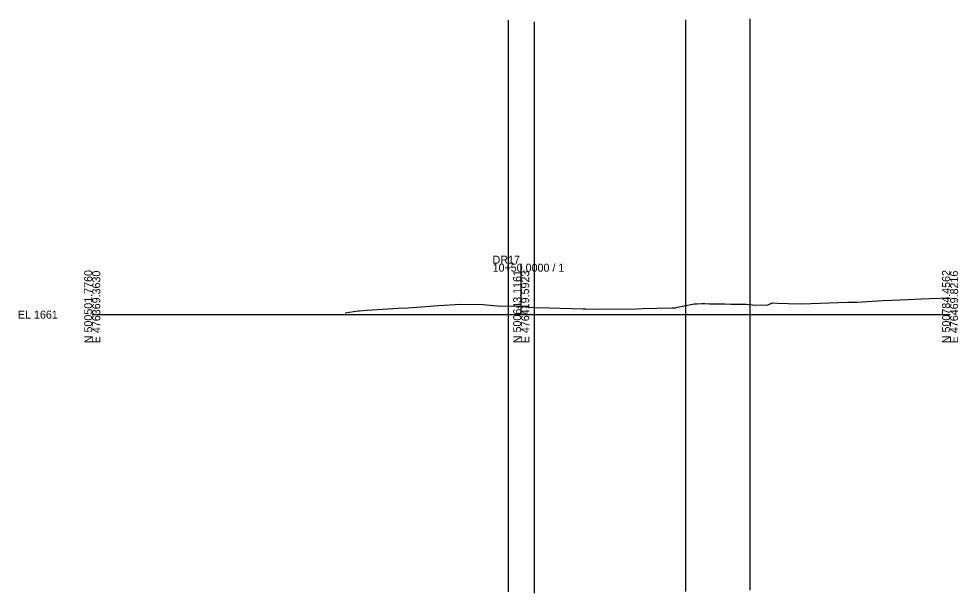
# Model space of a CAD drawing. Extents: x -26 to 303, y -96 to 3030.
# Drawn here: x -25.7 to 302.8, y 902.5 to 1103.5 of the extents above; entities that cross this region are included whole.
import ezdxf

# ---------------------------------------------------------------- set-up
doc = ezdxf.new("R2010")
doc.units = 0
for name, color, linetype in [('Exist Cross Section Cell', 7, 'Continuous'), ('Exist XS Center Line Elevation Label', 7, 'Continuous'), ('Exist XS Ground Line', 7, 'Continuous'), ('Scratch_Level_2', 7, 'Continuous')]:
    doc.layers.add(name, color=color, linetype=linetype)

msp = doc.modelspace()

# ---------------------------------------------------------------- linework, layer by layer
at = {"layer": 'Exist Cross Section Cell'}
for p, q in [((150, 1000), (150, 1017.83)), ((0, 1000), (150, 1000)), ((150, 1000), (300, 1000))]:
    msp.add_line(p, q, dxfattribs=at)
at = {"layer": 'Exist XS Ground Line'}
msp.add_lwpolyline([(88.47, 1000.62), (92.95, 1001.3), (93.29, 1001.34), (96, 1001.52), (106.99, 1002.25), (110.52, 1002.42), (121.04, 1003.23), (128.9, 1003.69), (136.71, 1003.5), (142.72, 1003.02), (147.65, 1003.03), (150, 1002.85), (154.4, 1002.51), (159.68, 1002.4), (171.69, 1002.03), (172.57, 1001.99), (175.51, 1001.94), (190.33, 1002), (192.4, 1002.17), (202.64, 1002.37), (203.97, 1002.43), (204.65, 1002.57), (205.21, 1002.68), (210.49, 1003.74), (210.98, 1003.76), (211.5, 1003.79), (213.21, 1003.85), (214.27, 1003.85), (215.87, 1003.83), (216.22, 1003.83), (217.21, 1003.83), (218.51, 1003.83), (219.36, 1003.82), (219.9, 1003.8), (221.14, 1003.75), (223.31, 1003.72), (224.02, 1003.71), (224.66, 1003.7), (225.98, 1003.68), (226.45, 1003.67), (227.63, 1003.66), (228.65, 1003.63), (230.93, 1003.49), (232.06, 1003.33), (236.22, 1003.43), (237.9, 1004.08), (239.52, 1004.07), (243.41, 1003.92), (248.07, 1003.75), (264.08, 1004.35), (267.35, 1004.4), (276.38, 1004.9), (279.48, 1005.04), (285.11, 1005.29), (290.1, 1005.5), (292.84, 1005.62), (300, 1005.94)], dxfattribs=at)
at = {"layer": 'Scratch_Level_2'}
for p, q in [((145.5, 1103.03), (145.5, 903.03)), ((154.5, 1102.51), (154.5, 902.51)), ((207.41, 1103.12), (207.41, 903.12)), ((230.01, 1103.55), (230.01, 903.55))]:
    msp.add_line(p, q, dxfattribs=at)

# ---------------------------------------------------------------- texts
at = {"layer": 'Exist Cross Section Cell'}
for s, p in [('DR17', (140, 1017.83)), ('10+50.0000 / 1', (140, 1015.03)), ('EL 1661', (-26, 998.6))]:
    msp.add_text(s, height=2.8, dxfattribs=at).set_placement(p)
for s, p in [('N 500501.7760', (0, 990)), ('E 476369.3630', (2.8, 990)), ('N 500643.1161', (150, 990)), ('E 476419.5923', (152.8, 990)), ('N 500784.4562', (300, 990)), ('E 476469.8216', (302.8, 990))]:
    msp.add_text(s, height=2.8, rotation=90, dxfattribs=at).set_placement(p)
at = {"layer": 'Exist XS Center Line Elevation Label'}
msp.add_text('1663.85', height=0.75, dxfattribs=at).set_placement((148.22, 1000.1))

doc.saveas('drawing.dxf')
